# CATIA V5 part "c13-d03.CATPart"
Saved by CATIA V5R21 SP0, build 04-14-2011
Part number: Part1
Bounding box of the stored display mesh (mm): x 0 to 136, y 0 to 120, z 0 to 120
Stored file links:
  D:\CATIA V5R21 E-RESOURCES\CATIA-V5R21\catia-v5r21-Prts\c13_catia_v5r21_prt\c13_catia_v5r21_figr_13-15 & 16\c13-d03.CATPart
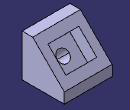
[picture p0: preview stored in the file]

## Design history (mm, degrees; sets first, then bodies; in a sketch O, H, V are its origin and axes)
Body1 (main body)
  Sketch1 on yz-plane, origin (0, 0, 0), H (0, 1, 0), V (0, 0, 1)
    line L1 (0, 0) -> (0, 120)
    line L2 (0, 120) -> (30, 120)
    line L3 (30, 120) -> (120, 30)
    line L4 (120, 30) -> (120, 0)
    point P4 (120, 0)
    line L5 (120, 0) -> (0, 0)
    length L1 = 120
    length L5 = 120
    length L4 = 30
    length L2 = 30
    vertical: L1 V, L4 V
    horizontal: L2 H, L5 H
    coincidence: P4 H
  Pad1: profile Sketch1, direction (1, 0, 0), length 136
  Sketch2 on face of Pad1, origin (0, 75, 75), H (-1, 0, 0), V (0, -0.7071, 0.7071)
    line L1 (-111.9577, 36.0679) -> (-24.0423, 36.0679)
    line L2 (-24.0423, 36.0679) -> (-24.0423, -36.0679)
    line L3 (-24.0423, -36.0679) -> (-111.9577, -36.0679)
    line L4 (-111.9577, -36.0679) -> (-111.9577, 36.0679)
    construction line L5 (-136, 63.6396) -> (0, -63.6396)
    point P5 (-136, 63.6396)
    point P6 (0, -63.6396)
    reference projected point E1 (0, -63.6396) from vertex [face of Pad1 | face of Pad1 | face of Pad1]
    reference projected point E2 (-136, 63.6396) from vertex [face of Pad1 | face of Pad1 | face of Pad1]
    axis line L6 (-111.9577, -36.0679) -> (-24.0423, 36.0679)
    point P7 (-68, 0)
    horizontal: L1 H, L3 H
    vertical: L2 V, L4 V
    coincidence: E1 P6, P5 E2
    midpoint: P7 L5, P7 L6
  Pocket1: profile Sketch2, direction (0, -0.7071, -0.7071), length 37
  Sketch3 on face of Pocket1, origin (0, 48.837, 48.837), H (-1, 0, 0), V (0, -0.7071, 0.7071)
    axis line L1 (-24.0423, -36.0679) -> (-111.9577, 36.0679)
    point P1 (-24.0423, -36.0679)
    point P2 (-111.9577, 36.0679)
    reference projected point E1 (-24.0423, -36.0679) from vertex [face of Pocket1 | face of Pad1 | face of Pocket1]
    reference projected point E2 (-111.9577, 36.0679) from vertex [face of Pocket1 | face of Pad1 | face of Pocket1]
    circle A1 centre (-68, 0) radius 17.073
    point P3 (-68, 0)
    point P4 (-50.927, 0)
    coincidence: P1 E1, P2 E2, A1 P4, P4 H
    midpoint: P3 L1
  Pocket2: profile Sketch3, direction (0, -0.7071, -0.7071), through (limit type 3)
